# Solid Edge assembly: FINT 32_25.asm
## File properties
Title: Zylinder
Author: bmolnar
Template: iso assembly.asm
Last saved by: bmolnar
Revision: 11
Application: Solid Edge
Username: bmolnar
Dokumentum tartalom típus: 1
Document Number: FINT 32/25
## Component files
hrungsstange.par
Profilrohr.par
Platte.par
Kolbenstange.par
Kit_1.par
Kit_2.par
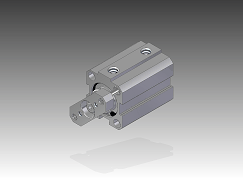
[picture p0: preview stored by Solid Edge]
